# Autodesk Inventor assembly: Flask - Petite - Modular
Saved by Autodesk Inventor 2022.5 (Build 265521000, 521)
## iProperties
Created: 2025-01
Part Number: Flask - Petite - Modular
Document SubType Name: Assembly
Designer: AdminForWorker
Title: Flask - Petite - Modular v9
Author: AdminForWorker
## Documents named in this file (4)
- c:\worker\convert-fusion-r06-cosv3\tmp\job-1\29\temp\files\cf144801-3b46-47ca-b193-809adda3b317\870cf54b-908c-4474-8781-1b85f4aae7f1.iam
- c:\worker\convert-fusion-r06-cosv3\tmp\job-1\29\temp\files\cf144801-3b46-47ca-b193-809adda3b317\Modular - Placebo - Bayonet Connector v4.ipt
- c:\worker\convert-fusion-r06-cosv3\tmp\job-1\29\temp\files\cf144801-3b46-47ca-b193-809adda3b317\Flask Petite Modular.ipt
- c:\worker\convert-fusion-r06-cosv3\tmp\job-1\29\temp\files\cf144801-3b46-47ca-b193-809adda3b317\Modular - Placedo - Cord Set v4.ipt
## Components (3 placed, 3 different names)
1. Modular - Placebo - Bayonet Connector v4:1
2. Flask Petite Modular:1
3. Modular - Placedo - Cord Set v4:1
